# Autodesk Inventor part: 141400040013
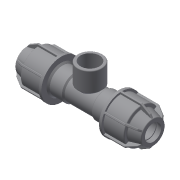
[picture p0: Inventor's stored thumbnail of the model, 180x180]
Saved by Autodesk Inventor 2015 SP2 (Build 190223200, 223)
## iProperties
Created: 2017-08
Part Number: 141400040013
Material: Generic
Description: PLASSON L.14 TEE FEMALE ADAPTOR (SILVER) 40 x 1.1/4" x 40
Document SubType Name: Modeling
Designer: KIM
Density: 1 g/cm^3
Appearance: Default
Author: KIM
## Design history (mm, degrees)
derived "141400.ipt"
feature "Solid1::141400.ipt"
feature "Solid2::141400.ipt"
tag "TaggingFeature1"
body "Solid1"
other parameters: "d2" = 62, "d4" = 15 deg, "d5" = 40.92, "d6" = 13.5036, "d10" = 73, "d16" = 40.8, "d17" = 3.1, "d22" = 64, "d24" = 3.1, "d25" = 65.7, "d26" = 54.75, "d27" = 3.1, "d28" = 135 deg, "d29" = 1.86, "d31" = 2, "d46" = 150 deg, "d49" = 3.65, "d50" = 0, "d58" = 1.2, "d61" = 360 deg, "d63" = 36, "d64" = 86.5, "d80" = 57.6, "d81" = 3.2, "d84" = 3.1, "d94" = 67, "d95" = 38.952, "d96" = 50.6376, "d97" = 25, "d98" = 36, "d99" = 45.57384, "d100" = 135 deg, "d108" = 2, "d111" = 0, "G_" = 38.952, "E_" = 73, "H_" = 173, "l_" = 62, "l_2" = 25, "A_" = 67
